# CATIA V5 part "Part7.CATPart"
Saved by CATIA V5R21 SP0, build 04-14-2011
Part number: Part7
Bounding box of the stored display mesh (mm): x -1 to 1, y -71.999 to 71.999, z -72 to 125
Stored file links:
  C:\Users\RIAD MAHAMUD PIASH\Desktop\Part7.CATPart
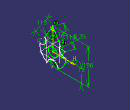
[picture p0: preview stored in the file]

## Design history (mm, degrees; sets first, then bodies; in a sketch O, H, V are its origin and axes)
Body1 (main body)
  Sketch1 on yz-plane, origin (0, 0, 0), H (0, 1, 0), V (0, 0, 1)
    arc A1 centre (0, 0) radius 72 from (30.2731, -65.3264) to (71.8071, 5.2668) ccw
    arc A2 centre (0, -72) radius 31 from (30.2731, -65.3264) to (-30.2731, -65.3264) ccw
    point P1 (0, -72)
    point P5 (43.1491, 50.2635)
    point P6 (64.8388, 32.4531)
    arc A3 centre (64.8388, 32.4531) radius 28.0651 from (43.1491, 50.2635) to (71.8071, 5.2668) ccw
    point P7 (-43.7736, 49.182)
    point P9 (-64.8388, 32.4531)
    arc A4 centre (-64.8388, 32.4531) radius 26.8998 from (-71.7109, 6.4459) to (-43.7736, 49.182) ccw
    point P12 (0, -71)
    arc A5 centre (0, -71) radius 31 from (30.2731, -64.3264) to (-30.2731, -64.3264) ccw
    arc A6 centre (0, 0) radius 72 from (-71.7109, 6.4459) to (-30.2731, -65.3264) ccw
    axis line L1 (0, 0) -> (0, 125)
    point P13 (0, 125)
    line L2 (-43.7736, 49.182) -> (0, 125)
    point P14 (0, 125)
    point P15 (43.7736, 49.182)
    line L3 (43.7736, 49.182) -> (0, 125)
    circle A7 centre (0, 0) radius 25
    radius A1 = 72
    radius A2 = 31
    distance P1 H = 72
    length L1 = 125
    distance P9 P13 = 113
    angle L3 L2 = 60
    distance P13 P6 = 113
    radius A7 = 25
    distance P13 P12 = 196
    coincidence: P1 V, P5 L3
    vertical: L1 V
    symmetry: P13 P14 L1, P7 P15 L1, L2 L3 L1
